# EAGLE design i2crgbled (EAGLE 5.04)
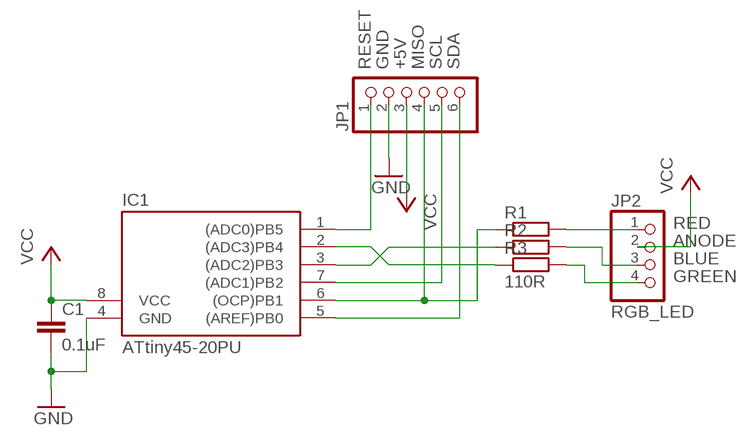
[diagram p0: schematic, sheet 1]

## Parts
C1  0.1uF  C5/2.5  [C5B2.5]
IC1  ATtiny45-20PU  TINY15LP  [DIL08]
JP1  PINHD-1X6  [1X06]
JP2  RGB_LED  PINHD-1X4  [1X04]
R1  R-EU_0207/7  [0207/7]
R2  R-EU_0207/7  [0207/7]
R3  110R  R-EU_0207/7  [0207/7]

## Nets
GND: C1.2 IC1.4(GND) JP1.2
N$1: IC1.1((ADC0)PB5) JP1.1
N$2: IC1.3((ADC2)PB3) R2.1
N$3: IC1.5((AREF)PB0) JP1.6
N$4: IC1.6((OCP)PB1) JP1.4 R1.1
N$5: IC1.7((ADC1)PB2) JP1.5
N$6: IC1.2((ADC3)PB4) R3.1
N$7: JP2.1 R1.2
N$8: JP2.3 R2.2
N$9: JP2.4 R3.2
VCC: C1.1 IC1.8(VCC) JP1.3 JP2.2

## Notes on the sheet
- RESET | GND | +5V | MISO | SCL | SDA
- RED
- ANODE
- BLUE
- GREEN

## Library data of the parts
C1 = capacitor-wima:C: CAPACITOR
IC1 = avr-5:TINY15L: MICROCONTROLLER 2.7 V 1 Kbytes FLASH 64 bytes EEPROM 4-channel 10 bit ADC
JP1 = pinhead:PINHD-1X6: PIN HEADER
JP2 = pinhead:PINHD-1X4: PIN HEADER
R1-R3 = rcl:R-EU_: RESISTOR, European symbol

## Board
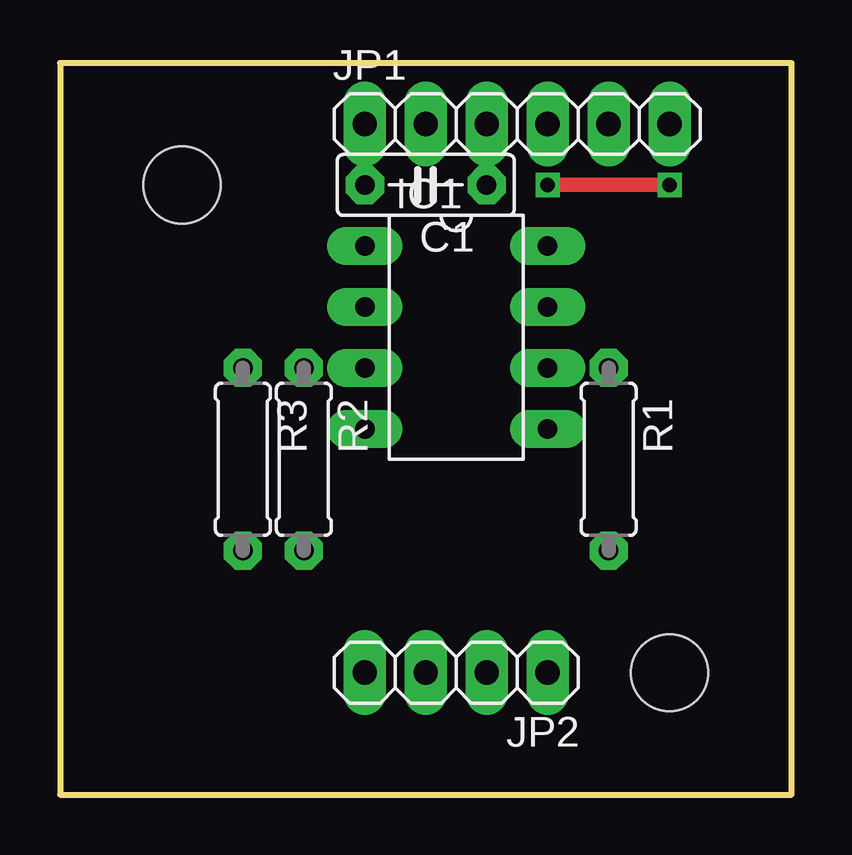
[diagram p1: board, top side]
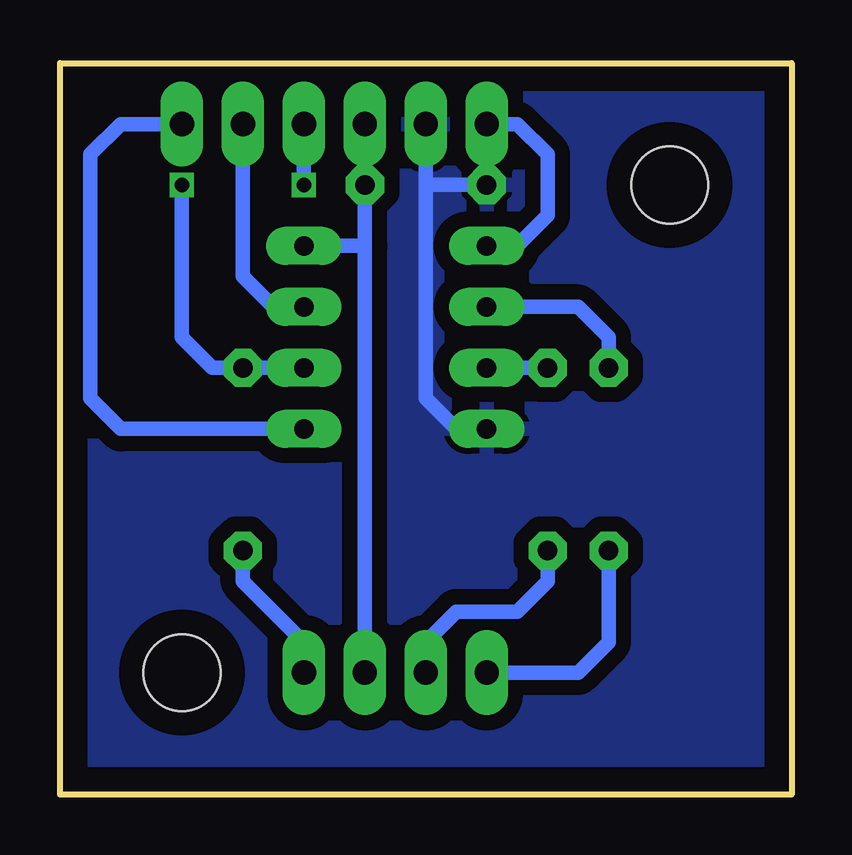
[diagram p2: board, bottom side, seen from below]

Size 30.48 x 30.48 mm. Coordinates in mm from the lower left corner, seen from the top.
Outline: 30.48,0 30.48,30.48 0,30.48 0,0 30.48,0
Copper layers (1*16): Top 0.035mm / dielectric 1.5mm / Bottom 0.035mm
Design rules "default *": minimum track width 10mil, minimum drill 24mil, track to track 25mil, track to pad 25mil, pad to pad 25mil, via to via 25mil, smd to smd 25mil, copper to edge 40mil, drill to drill 8mil, minimum pad ring 15mil, minimum via ring 8mil, stop-mask expansion 4mil, vias tented up to drill 0mil, thermal gap 10mil
Holes 3.2 mm at 25.4,5.08 5.08,25.4

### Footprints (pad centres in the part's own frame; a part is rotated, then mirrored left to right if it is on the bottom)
C5B2.5 = drill 0.813 pad 1.6 octagon: 1 -2.54,0; 2 2.54,0
DIL08 = drill 0.813 long: 1 -3.81,-3.81; 2 -1.27,-3.81; 3 1.27,-3.81; 4 3.81,-3.81; 5 3.81,3.81; 6 1.27,3.81; 7 -1.27,3.81; 8 -3.81,3.81
1X06 = drill 1.016 long: 1 -6.35,0; 2 -3.81,0; 3 -1.27,0; 4 1.27,0; 5 3.81,0; 6 6.35,0
1X04 = drill 1.016 long: 1 -3.81,0; 2 -1.27,0; 3 1.27,0; 4 3.81,0
0207/7 = drill 0.813 octagon: 1 -3.81,0; 2 3.81,0

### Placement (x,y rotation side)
C1  15.24,25.4 180 top
IC1  16.51,19.05 270 top
JP1  19.05,27.94 0 top
JP2  16.51,5.08 180 top
R1  22.86,13.97 270 top
R2  10.16,13.97 270 top
R3  7.62,13.97 270 top

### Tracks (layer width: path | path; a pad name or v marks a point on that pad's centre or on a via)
GND
  Bottom 0.61: 15.24,25.4 15.24,16.51 13.97,15.24 IC1.4 | 15.24,25.4 JP1.2 | 15.24,25.4 C1.2
  pour Bottom: 0,30.48 30.48,30.48 30.48,0 0,0
N$1
  Bottom 0.61: IC1.1 11.43,22.86 10.16,24.13 10.16,26.67 11.43,27.94 JP1.1
N$2
  Bottom 0.61: R2.1 IC1.3
N$3
  Bottom 0.61: IC1.5 27.94,15.24 29.21,16.51 29.21,26.67 27.94,27.94 JP1.6
N$4  (via drill 0.6)
  Top 0.61: v25.4,25.4 v20.32,25.4
  Bottom 0.61: R1.1 IC1.6 24.13,17.78 25.4,19.05 v25.4,25.4 | v20.32,25.4 JP1.4
N$5
  Bottom 0.61: IC1.7 21.59,20.32 22.86,21.59 JP1.5
N$6
  Bottom 0.61: IC1.2 8.89,20.32 7.62,19.05 R3.1
N$7
  Bottom 0.61: R1.2 22.86,8.89 20.32,6.35 JP2.1
N$8
  Bottom 0.61: R2.2 10.16,8.89 11.43,7.62 13.97,7.62 15.24,6.35 JP2.3
N$9
  Bottom 0.61: JP2.4 8.89,5.08 7.62,6.35 R3.2
VCC
  Bottom 0.61: JP2.2 17.78,22.86 | JP1.3 C1.1 17.78,22.86 | 17.78,22.86 IC1.8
